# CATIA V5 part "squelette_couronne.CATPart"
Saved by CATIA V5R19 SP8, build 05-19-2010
Part number: squelette_couronne
Publications: "Plan.1", "Point.3", "Esquisse.1"
Bounding box of the stored display mesh (mm): x 43.851 to 83, y 0 to 317.961, z 0 to 136.954
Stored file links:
  G:\EU_thinkMotion\CFAO_2010\MMS_groupe3\MMS_groupe3\A reprendre\amenand\amenand\squelette_couronne.CATPart
  F:\thinkmotion CFAO v12.1\essuie_glace.CATProduct
  G:\EU_thinkMotion\CFAO_2010\MMS_groupe3\MMS_groupe3\A reprendre\amenand\amenand\bati.CATPart
  G:\EU_thinkMotion\CFAO_2010\MMS_groupe3\MMS_groupe3\A reprendre\amenand\amenand\balancier.CATPart
  G:\EU_thinkMotion\CFAO_2010\MMS_groupe3\MMS_groupe3\A reprendre\amenand\amenand\squelette_de_base.CATPart
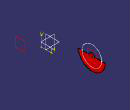
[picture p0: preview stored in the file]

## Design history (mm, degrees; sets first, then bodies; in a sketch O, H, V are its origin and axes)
Set1
  DatumSurface1: linked copy from another document
  Point1: linked copy from another document
  Plane1: linked copy from another document
Set2 "set géométrique.8"
  Point2: type OnPlane, Support DatumSurface1, RefPoint Point1, H 0, V 0, Direction (0, 1, 0)
  Plane2: type OffsetPt, RefPlane Plane1, RefPoint Point2
  Sketch1 on Plane2, origin (43.8512, 0, 0), H (0, 1, 0), V (0, 0, 1)
    circle A1 centre (251.964, 88.354) radius 48.6
    point P1 (251.964, 88.354)
    reference projected point E1 (251.964, 88.354) from Point1
    radius A1 = 48.6
    coincidence: P1 E1
Body1 (main body)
